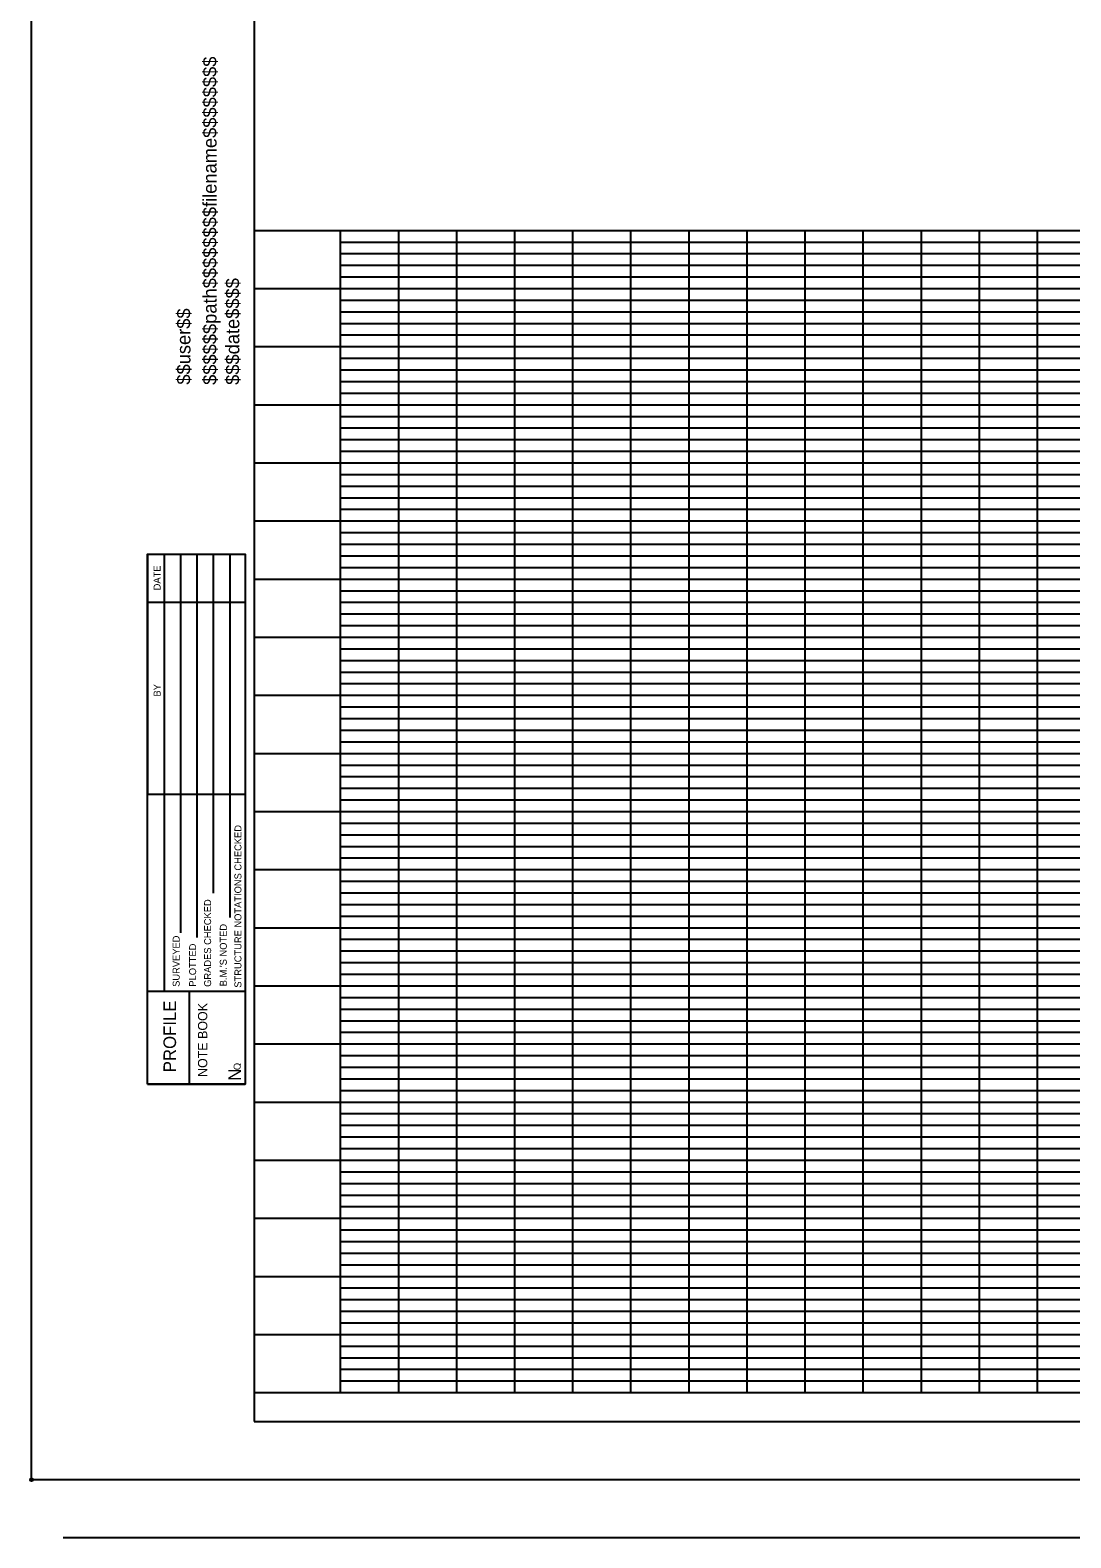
# Model space of a CAD drawing. Extents: x -184 to 1613, y -563 to 588.
# Drawn here: x -184 to 264, y -563 to 86 of the extents above; entities that cross this region are included whole.
import ezdxf

# ---------------------------------------------------------------- set-up
doc = ezdxf.new("R2010")
doc.units = 0
for name, color, linetype in [('RD_SHT_Bndy', 7, 'Continuous'), ('RD_SHT_ID', 7, 'Continuous'), ('RD_SHT_IplotShp', 7, 'Continuous'), ('RD_SHT_MjGrid', 7, 'Continuous'), ('RD_SHT_MnGrid', 7, 'Continuous'), ('RD_SHT_Snap', 7, 'Continuous'), ('RD_SHT_SubGrid', 7, 'Continuous'), ('RD_SHT_TX', 7, 'Continuous')]:
    doc.layers.add(name, color=color, linetype=linetype)

msp = doc.modelspace()

# ---------------------------------------------------------------- linework, layer by layer
at = {"layer": 'RD_SHT_Bndy'}
for p, q in [((-87, 537.5), (-87, -512.5)), ((-87, 0), (1588, 0)), ((-50, 0), (-50, -500)), ((-132.95, -139.3), (-132.95, -242.5)), ((-125.85, -139.3), (-125.85, -327.25)), ((-118.8, -139.3), (-118.8, -302.2)), ((-111.7, -139.3), (-111.7, -304.2)), ((-104.65, -139.3), (-104.65, -285.1)), ((-97.55, -139.3), (-97.55, -295.65)), ((-132.95, -159.95), (-90.95, -159.95)), ((-132.95, -242.5), (-90.95, -242.5)), ((-132.95, -327.3), (-90.95, -327.3)), ((-132.95, -367.3), (-132.95, -327.3)), ((-114.95, -367.3), (-114.95, -327.3)), ((-132.95, -367.3), (-90.95, -367.3)), ((-87, -500), (1588, -500)), ((-87, -512.5), (1588, -512.5)), ((1590.65, -537.5), (-169.35, -537.5)), ((1590.65, -562.5), (-169.35, -562.5))]:
    msp.add_line(p, q, dxfattribs=at)
msp.add_lwpolyline([(-132.95, -367.3), (-132.95, -139.3), (-90.95, -139.3), (-90.95, -367.3)], close=True, dxfattribs=at)
at = {"layer": 'RD_SHT_IplotShp'}
msp.add_lwpolyline([(-182.9, 562.5), (1613, 562.5), (1613, -537.5), (-182.9, -537.5)], close=True, dxfattribs=at)
msp.add_circle((-182.9, -537.5), 0.607, dxfattribs=at)
at = {"layer": 'RD_SHT_MjGrid'}
for p, q in [((0, 0), (0, -500)), ((50, 0), (50, -500)), ((100, 0), (100, -500)), ((150, 0), (150, -500)), ((200, 0), (200, -500)), ((250, 0), (250, -500)), ((-87, -50), (1588, -50)), ((-87, -100), (1588, -100)), ((-87, -150), (1588, -150)), ((-87, -200), (1588, -200)), ((-87, -250), (1588, -250)), ((-87, -300), (1588, -300)), ((-87, -350), (1588, -350)), ((-87, -400), (1588, -400)), ((-87, -450), (1588, -450))]:
    msp.add_line(p, q, dxfattribs=at)
at = {"layer": 'RD_SHT_MnGrid'}
for p, q in [((-25, 0), (-25, -500)), ((25, 0), (25, -500)), ((75, 0), (75, -500)), ((125, 0), (125, -500)), ((175, 0), (175, -500)), ((225, 0), (225, -500)), ((-87, -25), (1588, -25)), ((-87, -75), (1588, -75)), ((-87, -125), (1588, -125)), ((-87, -175), (1588, -175)), ((-87, -225), (1588, -225)), ((-87, -275), (1588, -275)), ((-87, -325), (1588, -325)), ((-87, -375), (1588, -375)), ((-87, -425), (1588, -425)), ((-87, -475), (1588, -475))]:
    msp.add_line(p, q, dxfattribs=at)
at = {"layer": 'RD_SHT_Snap'}
msp.add_line((-182.9, -537.5), (-182.9, 562.5), dxfattribs=at)
at = {"layer": 'RD_SHT_SubGrid'}
for p, q in [((-49.95, -5), (1549.8, -5)), ((-49.95, -10), (1549.25, -10)), ((-49.95, -15), (1549.8, -15)), ((-49.9, -20), (1549.8, -20)), ((-49.95, -30), (1549.8, -30)), ((-49.95, -35), (1548.75, -35)), ((-49.95, -40), (1549.25, -40)), ((-49.95, -45), (1549.8, -45)), ((-49.95, -55), (1549.8, -55)), ((-49.95, -60), (1549.8, -60)), ((-49.95, -65), (1549.25, -65)), ((-49.95, -70), (1549.8, -70)), ((-49.95, -80), (1548.75, -80)), ((-49.95, -85), (1548.75, -85)), ((-49.95, -90), (1549.25, -90)), ((-49.95, -95), (1549.25, -95)), ((-49.95, -105), (1548.75, -105)), ((-49.95, -110), (1549.25, -110)), ((-49.95, -115), (1548.75, -115)), ((-49.9, -120), (1549.8, -120)), ((-49.95, -130), (1549.25, -130)), ((-49.95, -135), (1549.25, -135)), ((-49.95, -140), (1549.25, -140)), ((-49.95, -145), (1549.25, -145)), ((-49.85, -155), (1548.75, -155)), ((-49.85, -160), (1548.75, -160)), ((-49.9, -165), (1549.25, -165)), ((-49.9, -170), (1549.25, -170)), ((-49.95, -180), (1549.25, -180)), ((-49.95, -185), (1549.25, -185)), ((-49.95, -190), (1548.75, -190)), ((-49.95, -195), (1549.25, -195)), ((-49.95, -195), (1549.25, -195)), ((-49.95, -205), (1549.8, -205)), ((-49.95, -210), (1549.8, -210)), ((-49.95, -215), (1549.8, -215)), ((-49.95, -220), (1549.8, -220)), ((-49.95, -230), (1549.8, -230)), ((-49.95, -235), (1549.8, -235)), ((-49.95, -240), (1549.8, -240)), ((-49.95, -245), (1549.8, -245)), ((-49.95, -255), (1549.85, -255)), ((-49.95, -260), (1549.85, -260)), ((-49.95, -265), (1549.85, -265)), ((-49.95, -270), (1549.85, -270)), ((-49.95, -280), (1549.85, -280)), ((-49.95, -285), (1549.85, -285)), ((-49.95, -290), (1549.85, -290)), ((-49.95, -295), (1549.85, -295)), ((-49.95, -305), (1549.85, -305)), ((-49.95, -310), (1549.85, -310)), ((-49.95, -315), (1549.85, -315)), ((-49.95, -320), (1549.85, -320)), ((-49.95, -330), (1549.85, -330)), ((-49.9, -330), (1549.85, -330)), ((-49.95, -335), (1549.85, -335)), ((-49.9, -340), (1549.6, -340)), ((-49.9, -345), (1549.6, -345)), ((-49.9, -355), (1549.8, -355)), ((-49.95, -360), (1549.95, -360)), ((-49.95, -365), (1549.95, -365)), ((-49.9, -370), (1549.95, -370)), ((-49.95, -380), (1549.95, -380)), ((-49.95, -385), (1549.95, -385)), ((-49.95, -390), (1549.95, -390)), ((-49.9, -395), (1549.95, -395)), ((-49.95, -405), (1549.95, -405)), ((-49.95, -410), (1549.95, -410)), ((-49.95, -415), (1549.95, -415)), ((-49.95, -420), (1549.85, -420)), ((-49.9, -430), (1549.6, -430)), ((-49.95, -435), (1549.85, -435)), ((-49.95, -440), (1549.85, -440)), ((-49.95, -445), (1549.85, -445)), ((-49.95, -460), (1549.85, -460)), ((-49.85, -455), (1549.85, -455)), ((-49.95, -465), (1549.85, -465)), ((-49.95, -470), (1549.85, -470)), ((-49.85, -480), (1549.85, -480)), ((-49.85, -485), (1549.85, -485)), ((-49.85, -490), (1549.85, -490)), ((-49.85, -495), (1549.85, -495))]:
    msp.add_line(p, q, dxfattribs=at)

# ---------------------------------------------------------------- texts
at = {"layer": 'RD_SHT_ID'}
for s, p in [('$$$$$$path$$$$$$$$filename$$$$$$$$', (-103.25, -66.45)), ('$$$date$$$$', (-93.45, -66.45)), ('$$user$$', (-114.5, -66.35))]:
    msp.add_text(s, height=5.88, rotation=90, dxfattribs=at).set_placement(p)
at = {"layer": 'RD_SHT_TX'}
for s, height, p in [('DATE', 3, (-127.35, -154.85)), ('BY', 3, (-127.35, -200.55)), ('STRUCTURE NOTATIONS CHECKED', 3, (-92.55, -325.8)), ('GRADES CHECKED', 3, (-105.6, -325.45)), ('SURVEYED', 3, (-119.15, -325.45)), ("B.M.'S NOTED", 3, (-98.85, -325.2)), ('PLOTTED', 3, (-112.05, -325.35)), ('PROFILE', 5.4, (-120.7, -362.2)), ('NOTE BOOK', 4, (-107.25, -364.2)), ('N', 5.4, (-92.8, -365.85)), ('O', 3, (-92.9, -361.3))]:
    msp.add_text(s, height=height, rotation=90, dxfattribs=at).set_placement(p)
msp.add_text('.', height=3, dxfattribs=at).set_placement((-93.55, -358.9))

doc.saveas('drawing.dxf')
